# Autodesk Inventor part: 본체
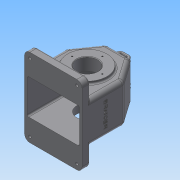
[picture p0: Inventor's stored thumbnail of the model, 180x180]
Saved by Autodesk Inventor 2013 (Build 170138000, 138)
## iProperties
Created: 2016-12
Part Number: 본체
Material: 일반
Document SubType Name: Modeling
Designer: Administrator
Density: 1 g/cm^3
Author: Administrator
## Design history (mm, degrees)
sketch "스케치1"
  geometry: L1 (-55, 0)-(-55, 80); L2 (-55, 80)-(-23.491, 125); L3 (-23.491, 125)-(23.491, 125); L4 (23.491, 125)-(55, 80); L5 (55, 80)-(55, 0); L6 (55, 0)-(-55, 0); L7 (-55, 15)-(55, 15); L8 (-55, 65)-(55, 65); 3 further points
  constraints: 16 end point, 4 parallel, 4 point on line, 2 coincident, 2 midpoint, 1 perpendicular, 1 vertical, 1 vertical alignment
  dimensions: "d0" = 80 distance of L5.end L4.end; "d2" = 125 distance between parallel lines of L6 L3; "d3" = 110 distance of L5.end L1.start; "d4" = 15 distance between parallel lines of L7 L6; "d5" = 65 distance between parallel lines of L6 L8; "d6" = 35 deg angle of L1 L2; "d7" = 35 deg angle of L5 L4
extrude "돌출1" new body sketch "스케치1" stored distance "d8" = 77; taper "d9" = 0 deg
extrude "돌출2" join sketch "스케치1" stored distance "d10" = 150; taper "d11" = 0 deg
feature "쉘1" dims "d12" = 15, "d13" = 5
sketch "스케치2"
  geometry: L1 (-55, 0)-(55, 0) reference; C1 r 37.5 at (0, 65); 2 further points
  constraints: 1 centre point, 1 midpoint, 1 vertical alignment
  dimensions: "d16" = 75 diameter of C1; "d17" = 65 distance from line of L1 C1.centre
extrude "돌출3" join sketch "스케치2" distance "d18" = 5; taper "d19" = 0 deg
sketch "스케치3"
  geometry: L1 (-55, 0)-(55, 0) reference; C1 r 31 at (0, 65); 2 further points
  constraints: 1 centre point, 1 midpoint, 1 vertical alignment
  dimensions: "d20" = 62 diameter of C1; "d21" = 65 distance from line of L1 C1.centre
extrude "돌출4" join sketch "스케치3" distance "d22" = 10; taper "d23" = 0 deg
node "작업 평면1"
sketch "스케치4"
  geometry: L1 (50, 13.424)-(20.888, 55) reference; L2 (20.888, 55)-(-20.888, 55) reference; L3 (-20.888, 55)-(-50, 13.424) reference; L4 (-50, 13.424)-(-50, -65) reference; L5 (-50, -65)-(-55, -65) reference; L6 (-55, -65)-(-55, 15) reference; L7 (-55, 15)-(-23.491, 60) reference; L8 (23.491, 60)-(55, 15) reference; L9 (55, 15)-(55, -65) reference; L10 (55, -65)-(50, -65) reference; L11 (50, -65)-(50, 13.424) reference; L12 (-23.491, 60)-(23.491, 60) reference; C1 r 27 at (0, 0); 1 further point
  constraints: 1 centre point, 1 vertical alignment
  dimensions: "d25" = 54 diameter of C1
extrude "돌출5" join sketch "스케치4" stored distance "d27" = 10; taper "d28" = 45 deg
hole "구멍1" diameter "d31" = 40; stored, may be unused: countersink angle "d35" = 90 deg, drill point angle "d37" = 118 deg; dims "d29" = 10, "d30" = 10, "d32" = 6, "d33" = 4, "d34" = 2, "d36" = 24
hole "구멍2" diameter "d40" = 40; stored, may be unused: countersink angle "d44" = 90 deg, drill point angle "d46" = 118 deg; dims "d38" = 10, "d39" = 10, "d41" = 6, "d42" = 4, "d43" = 2, "d45" = 15
chamfer "모따기1" distance "d47" = 1; stored, may be unused: second distance "d48" = 2, angle "d49" = 45 deg
sketch "스케치5"
  geometry: L1 (0, 0)-(0, 29); C1 r 21 at (0, 0) reference; 1 further point
  constraints: 2 end point, 1 vertical
  dimensions: "d50" = 29 distance of L1.start L1.end
hole "구멍3" sketch "스케치5" at (0, 29) diameter "d51" = 2.459; stored, may be unused: countersink angle "d55" = 90 deg, drill point angle "d57" = 118 deg; dims "d52" = 6, "d53" = 4, "d54" = 2, "d56" = 8
sketch "스케치6"
  geometry: L1 (0, 0)-(0, 26); C1 r 21 at (0, 0) reference; 1 further point
  constraints: 2 end point, 1 vertical
  dimensions: "d61" = 26 distance of L1.start L1.end
hole "구멍4" sketch "스케치6" at (0, 26) diameter "d62" = 2.459; stored, may be unused: countersink angle "d66" = 90 deg, drill point angle "d68" = 118 deg; dims "d63" = 6, "d64" = 4, "d65" = 2, "d67" = 8
fillet "모깎기3" dims "d72" = 8
fillet "모깎기4" dims "d73" = 10
fillet "모깎기5" dims "d74" = 3
fillet "모깎기6" dims "d75" = 3
fillet "모깎기7" dims "d76" = 10
fillet "모깎기8" dims "d77" = 3
sketch "스케치7"
  geometry: L1 (105.5, -76.847)-(95.5, -76.847) reference; 5 further points; 1 other entity
  constraints: 2 other
  dimensions: "d78" = 38.5 dimension on point (30.5, -31.847); "d79" = 45 distance from line of L1 point (30.5, -31.847)
feature "엠보싱1" sketch "스케치7" dims "d80" = 0.5, "d81" = 0
fillet "모깎기9" dims "d82" = 5
node "작업 평면2"
sketch "스케치8"
  geometry: L1 (-18.285, 125)-(18.285, 125) reference; L2 (26.477, 120.736)-(53.192, 82.583) reference; L3 (55, 76.847)-(55, 48.538) reference; L4 (55.5, 48.538)-(55.5, 48.515) reference; L5 (55, 48.515)-(55, 45.777) reference; L6 (55, 45.777)-(55.5, 45.777) reference; L7 (55.5, 45.777)-(55.5, 45.305) reference; L8 (55.5, 45.305)-(55, 45.305) reference; L9 (55, 45.305)-(55, 42.073) reference; L10 (55, 42.073)-(55.5, 42.073) reference; L11 (55.5, 42.073)-(55.5, 41.617) reference; L12 (55.5, 41.617)-(55, 41.617) reference; L13 (55, 41.617)-(55, 0) reference; L14 (55, 0)-(50, 0) reference; L15 (50, 0)-(50, 78.424) reference; L16 (50, 78.424)-(20.888, 120) reference; L17 (-20.888, 120)-(-49.096, 79.715) reference; L18 (-50, 76.847)-(-50, 0) reference; L19 (-50, 0)-(-55, 0) reference; L20 (-55, 0)-(-55, 76.847) reference; L21 (-53.192, 82.583)-(-26.477, 120.736) reference; L22 (-12.5, 125)-(-12.5, 140); L23 (-12.5, 140)-(12.5, 140); L24 (12.5, 140)-(12.5, 125); L25 (7.5, 125)-(7.5, 135); L26 (7.5, 135)-(-7.5, 135); L27 (-7.5, 135)-(-7.5, 125); L28 (-7.5, 125)-(7.5, 125); L29 (18.285, 125)-(-18.285, 125) reference; L30 (20.888, 120)-(-20.888, 120) reference; A1 r 10 centre (-18.285, 115) between (-18.285, 125) and (-26.477, 120.736) reference; A2 r 10 centre (18.285, 115) between (26.477, 120.736) and (18.285, 125) reference; A3 r 10 centre (45, 76.847) between (55, 76.847) and (53.192, 82.583) reference; A4 r 5 centre (-45, 76.847) between (-49.096, 79.715) and (-50, 76.847) reference; A5 r 10 centre (-45, 76.847) between (-53.192, 82.583) and (-55, 76.847) reference; 5 further points
  constraints: 14 end point, 4 midpoint, 2 horizontal alignment, 2 perpendicular, 2 point on line, 1 coincident, 1 collinear, 1 parallel, 1 vertical alignment, 2 other
  dimensions: "d84" = 25 distance between parallel lines of L24 L22; "d86" = 15 distance between parallel lines of L1 L23; "d87" = 5 distance between parallel lines of L24 L25
  node "절단 모서리 투영2"
extrude "돌출6" join sketch "스케치8" distance "d88" = 8; taper "d89" = 0 deg
fillet "모깎기10" dims "d90" = 8
fillet "모깎기11" dims "d91" = 1
extrude "돌출7" cut sketch "스케치8" distance "d93" = 8; taper "d94" = 0 deg
fillet "모깎기13" dims "d95" = 1
fillet "모깎기14" dims "d96" = 8
fillet "모깎기16" dims "d98" = 1
sketch "스케치9"
  geometry: A1 r 7 centre (0, 7) between (-7, 7) and (0, 0) reference; A2 r 7 centre (90, 7) between (90, 0) and (97, 7) reference; A3 r 10 centre (0, 137) between (0, 147) and (-10, 137) reference; A4 r 10 centre (90, 137) between (100, 137) and (90, 147) reference; 5 further points
  constraints: 4 coincident
hole "구멍5" sketch "스케치9" at (0, 7), (90, 7), (0, 137), (90, 137) diameter "d99" = 5; stored, may be unused: countersink angle "d103" = 90 deg, drill point angle "d105" = 118 deg; dims "d100" = 6, "d101" = 12, "d102" = 5, "d104" = 8
fillet "모깎기17" dims "d106" = 5
fillet "모깎기18" dims "d107" = 3
fillet "모깎기19" dims "d108" = 1
fillet "모깎기20" dims "d109" = 3
fillet "모깎기21" dims "d110" = 1
node "솔리드1"
pattern_circular "원형 패턴1" dims angle "d59" = 360 deg
pattern_circular "원형 패턴2" dims angle "d70" = 360 deg
mirror "대칭1"
node "절단 모서리 투영1"
other parameters: "d24" = -24, "d83" = 18
